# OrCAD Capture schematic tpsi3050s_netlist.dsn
size Custom
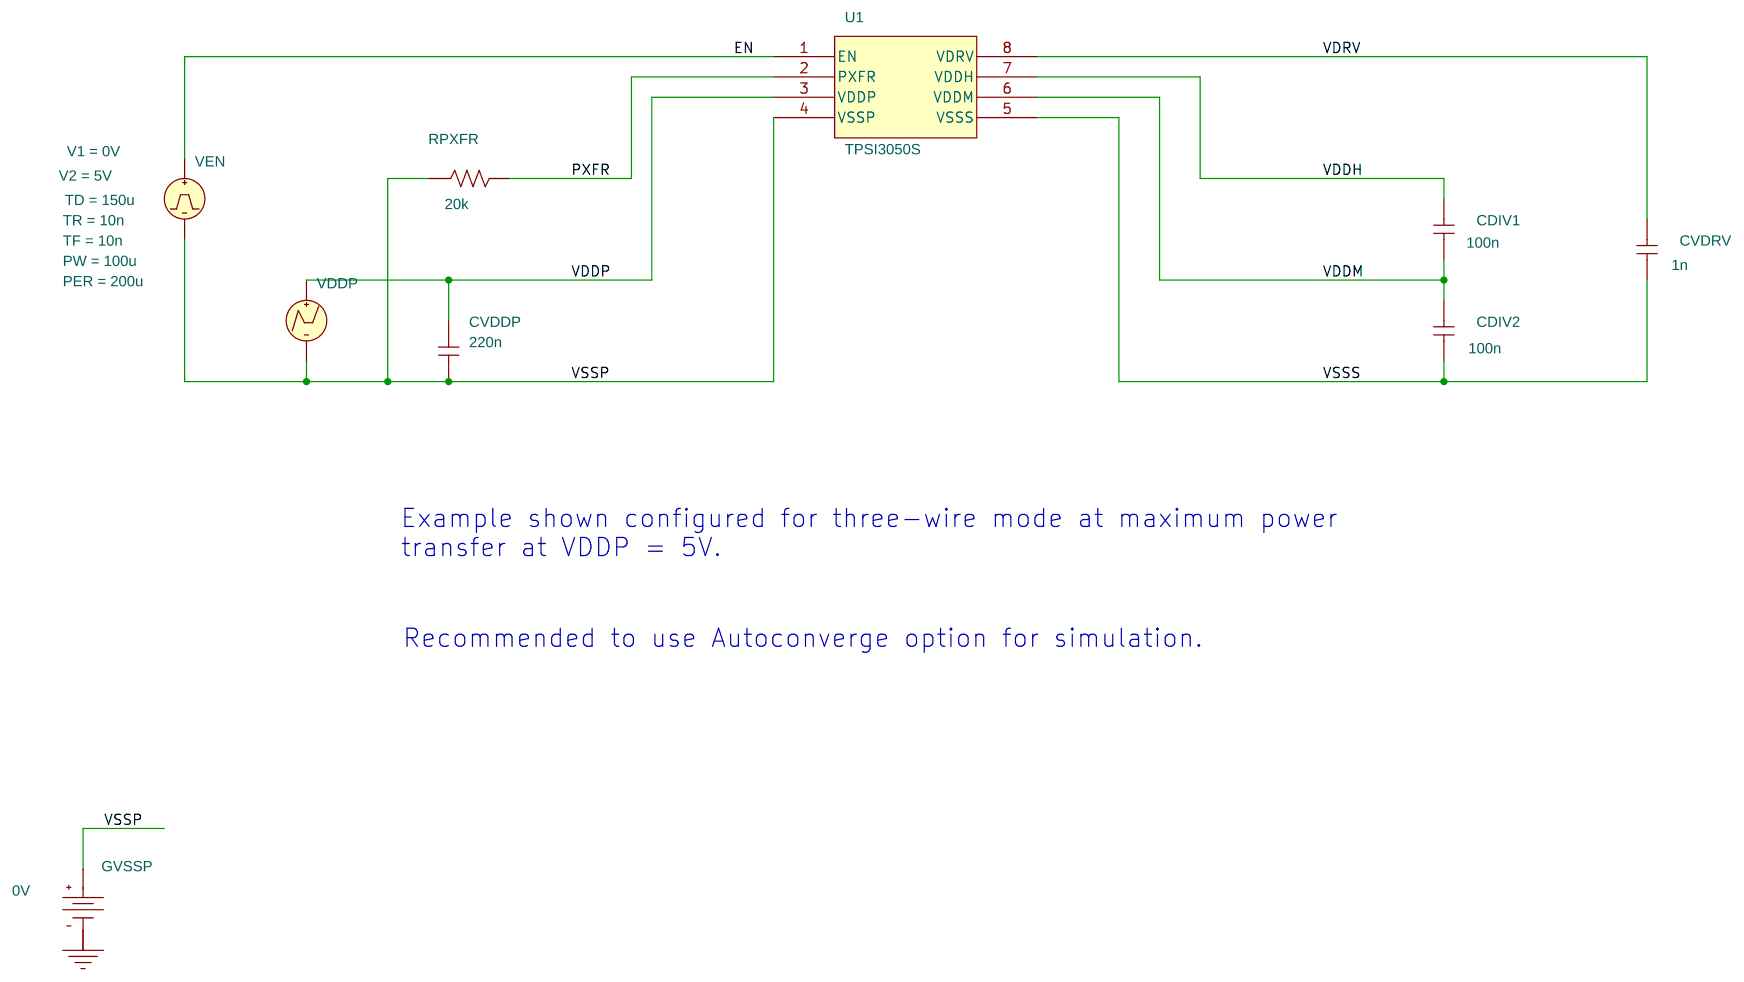
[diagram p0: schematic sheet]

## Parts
CDIV1  100n  [cap196]
CDIV2  100n  [cap196]
CVDDP  220n  [cap196]
CVDRV  1n  [cap196]
GVSSP  VDC
RPXFR  20k  [AXRC05]
U1  TPSI3050S
VDDP  VPWL
VEN  VPULSE

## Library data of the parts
CDIV1 CDIV2 CVDDP CVDRV = C
GVSSP = VDC: DC: 0V
RPXFR = R
U1 = TPSI3050S: PSpiceTemplate: X^@REFDES  %EN %PXFR %VDDP %VSSP %VDRV %VDDH %VDDM %VSSS @MODEL
VDDP = VPWL: T1: 0us; T2: 5us; T3: 5.1us; V1: 0V; V2: 0V; V3: 5V
VEN = VPULSE: PER: 200u; PW: 100u; TD: 150u; TF: 10n; TR: 10n; V1: 0V; V2: 5V

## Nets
VDDH: CDIV1.2 U1.7(VDDH)
VDDM: CDIV1.1 CDIV2.2 U1.6(VDDM)
VDDP: CVDDP.2 U1.3(VDDP) VDDP.1(+)
VSSP: CVDDP.1 GVSSP.0(+) RPXFR.1 U1.4(VSSP) VDDP.2(-) VEN.2(-)
VSSS: CDIV2.1 CVDRV.1 U1.5(VSSS)
0: GVSSP.1(-)
EN: U1.1(EN) VEN.1(+)
PXFR: RPXFR.2 U1.2(PXFR)
VDRV: CVDRV.2 U1.8(VDRV)

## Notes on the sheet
- Example shown configured for three-wire mode at maximum power
  transfer at VDDP = 5V.
- Recommended to use Autoconverge option for simulation.
